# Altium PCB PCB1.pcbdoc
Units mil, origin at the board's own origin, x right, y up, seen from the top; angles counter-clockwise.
Board outline 2952.76 x 2952.76 mil, 2 copper layers (Top Layer, Bottom Layer), stack 62.206 mil thick; 24 components, 35 nets, 97 pads, 20 vias.
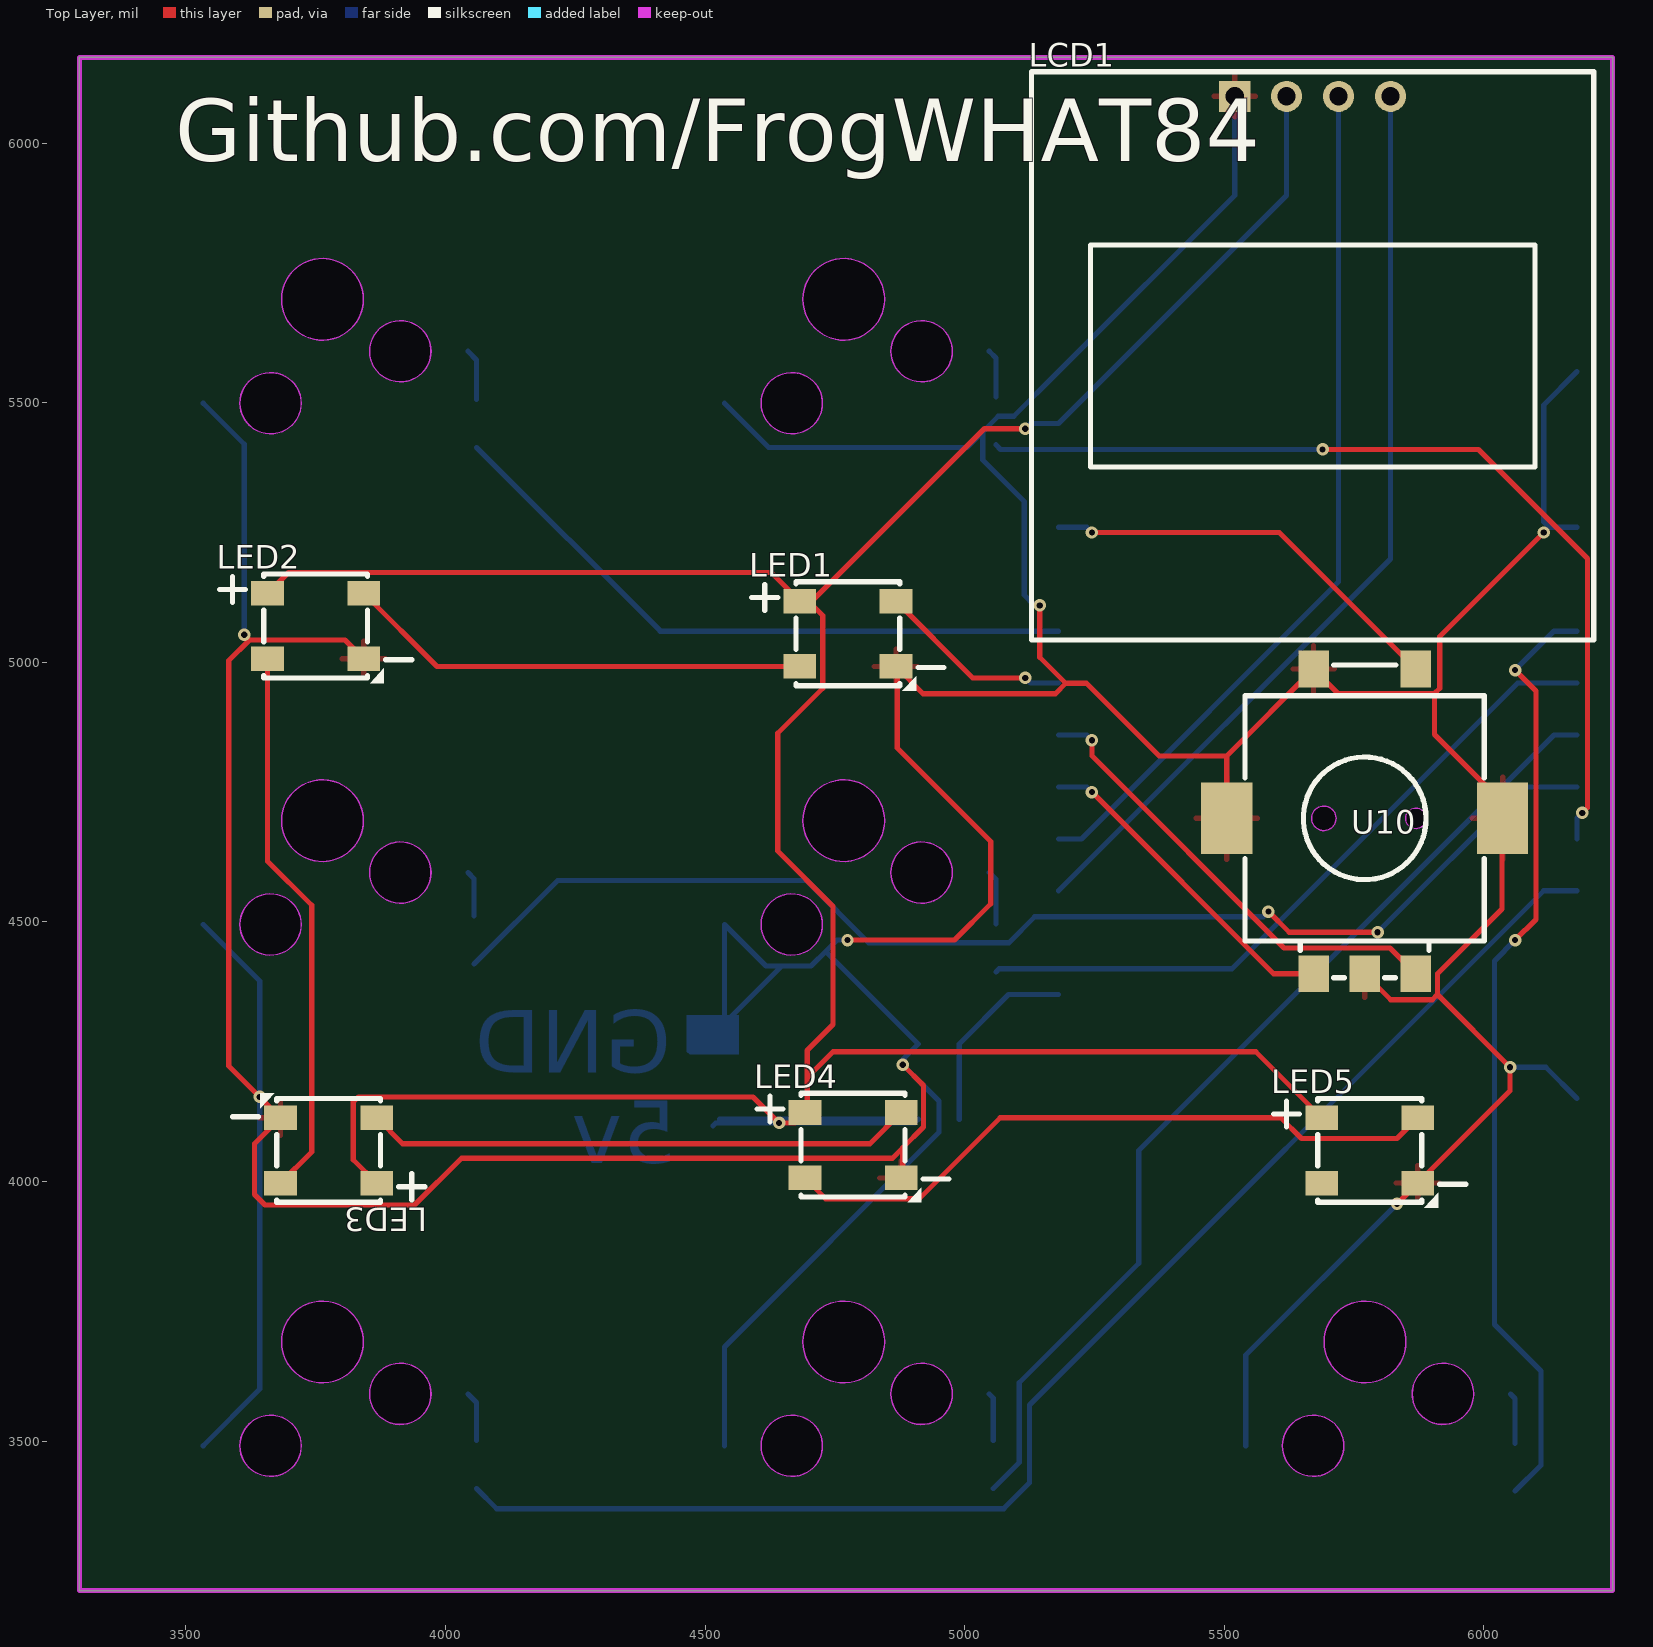
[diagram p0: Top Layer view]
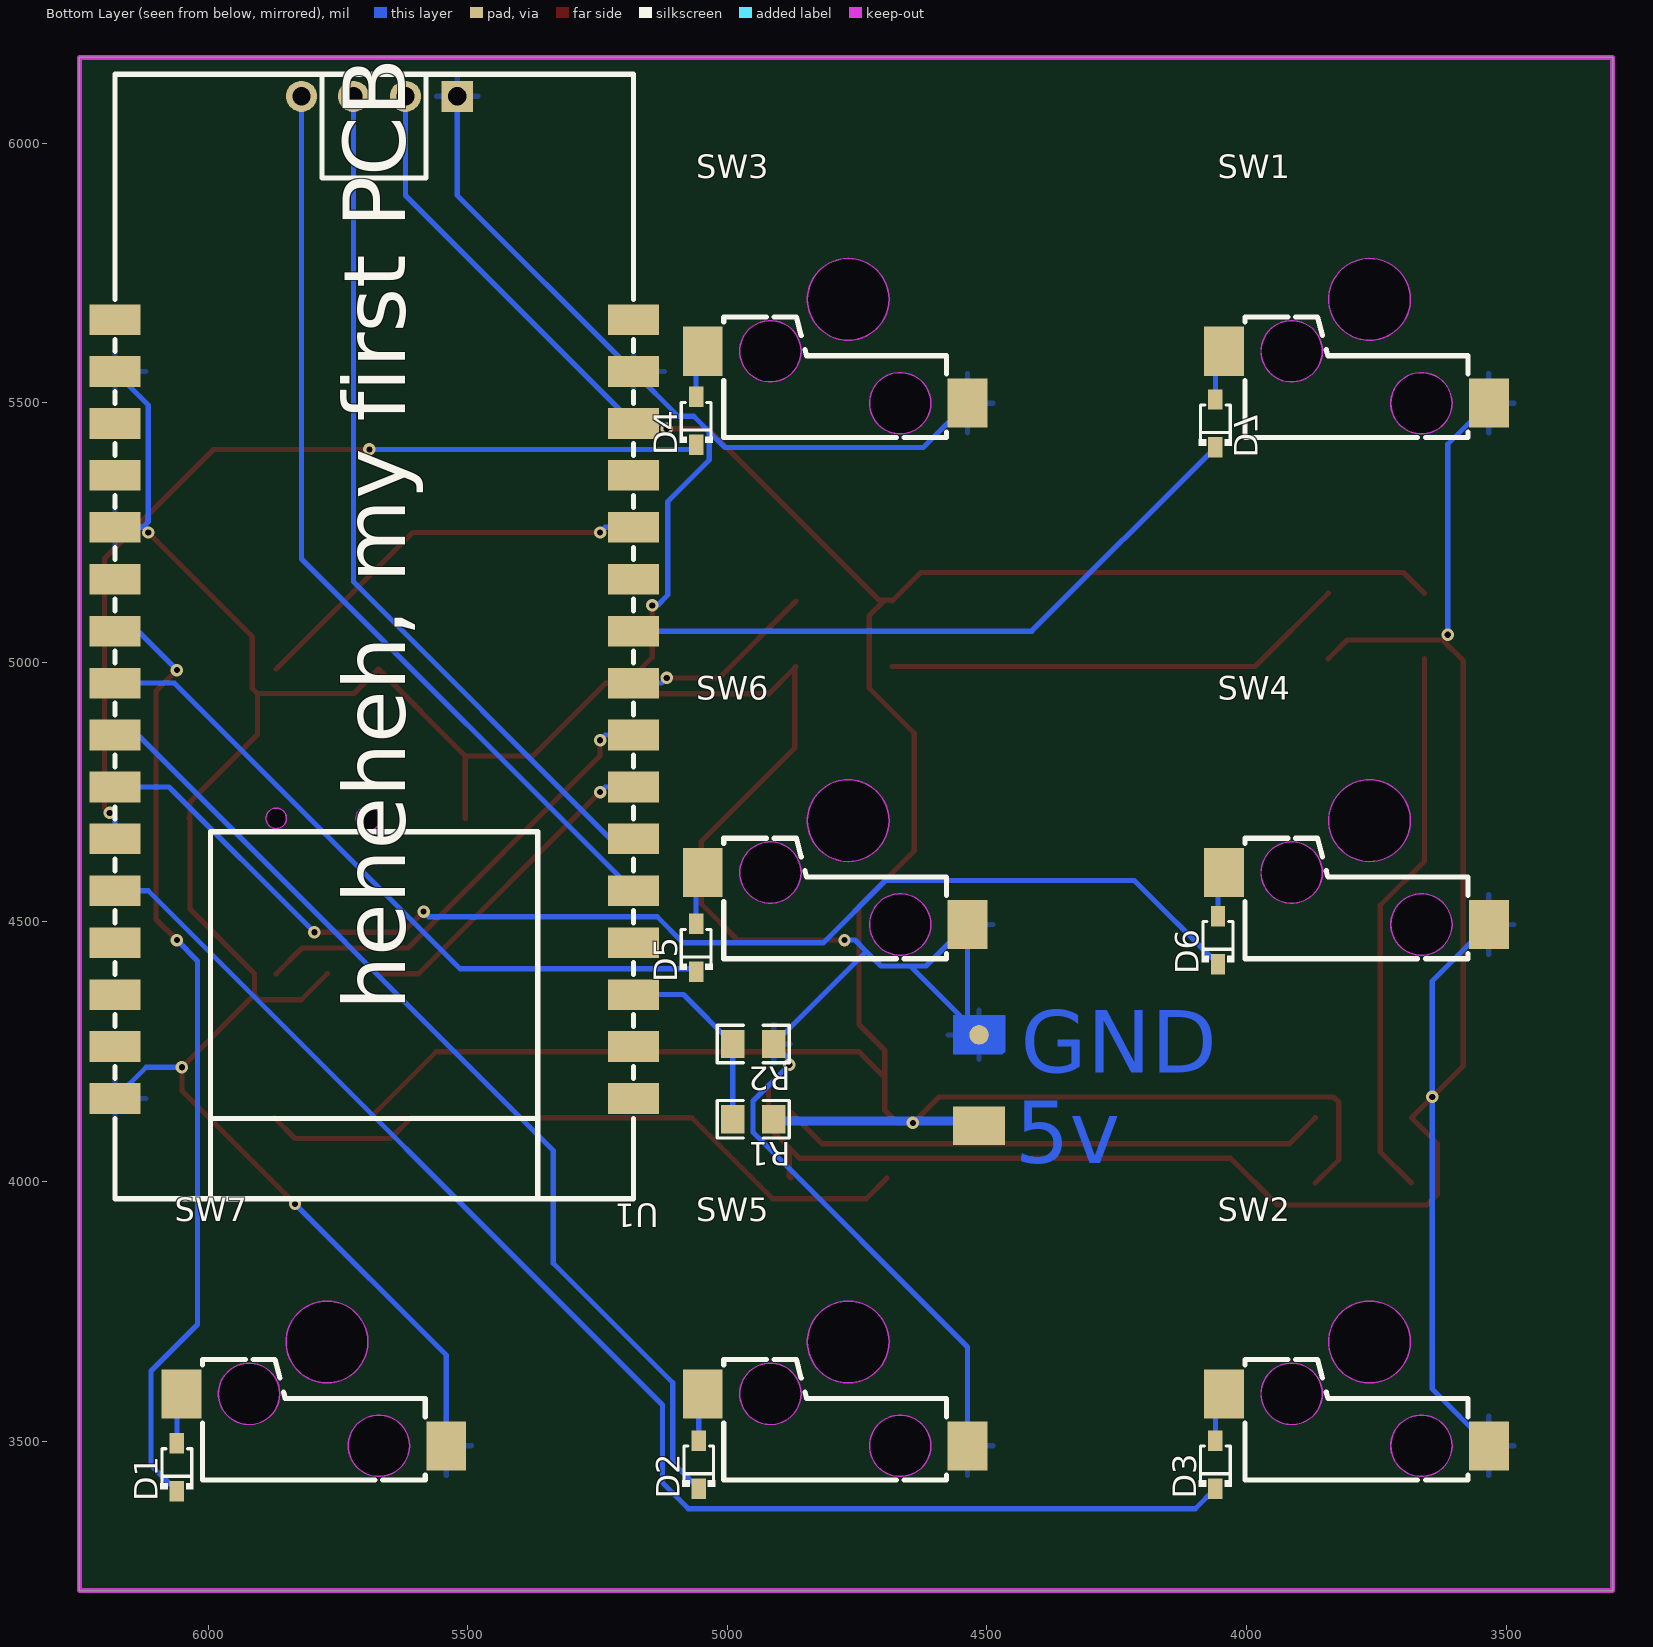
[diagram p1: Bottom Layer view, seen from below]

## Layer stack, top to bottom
Top Solder Mask Layer: solder mask 0.394, Dk 3.3
Top Layer: signal copper 1.379
Dielectric1: surface 59.449, FR4, Dk 4.5
Bottom Layer: signal copper 1.378
Bottom Solder Mask Layer: solder mask 0.394, Dk 3.3

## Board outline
3295,6165 3295,3212.24 6247.76,3212.24 6247.76,6165

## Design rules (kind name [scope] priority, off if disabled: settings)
BoardOutlineClearance copperThickness1oz [All] p0: genericclearance=10 ignorepadtopadclearanceinfootprint=FALSE except(0: Arc-SplitContinuation Track-SplitContinuation SMDPad-SplitContinuation THPad-SplitContinuation Via-SplitContinuation Fill-SplitContinuation Poly-SplitContinuation Region-SplitContinuation Text-SplitContinuation)
BoardOutlineClearance copperThickness2oz [All] p0: genericclearance=10 ignorepadtopadclearanceinfootprint=FALSE except(0: Arc-SplitContinuation Track-SplitContinuation SMDPad-SplitContinuation THPad-SplitContinuation Via-SplitContinuation Fill-SplitContinuation Poly-SplitContinuation Region-SplitContinuation Text-SplitContinuation)
BoardOutlineClearance otherClearance [All] p0: genericclearance=10 ignorepadtopadclearanceinfootprint=FALSE except(0: Arc-SplitContinuation Track-SplitContinuation SMDPad-SplitContinuation THPad-SplitContinuation Via-SplitContinuation Fill-SplitContinuation Poly-SplitContinuation Region-SplitContinuation Text-SplitContinuation)
Clearance copperThickness1oz [All] p1: gap=7 ignorepadtopadclearanceinfootprint=FALSE
Clearance copperThickness2oz [(InNet('+5V'))] p1: gap=7 ignorepadtopadclearanceinfootprint=FALSE
Clearance otherClearance [All] p1: gap=7 ignorepadtopadclearanceinfootprint=FALSE
DiffPairsRouting differentialPair [All] p1: maxuncoupledlength=10 minlimit=6 maxlimit=Infinity mostfreqgap=6 toplayer_minwidth=5 toplayer_prefwidth=10 toplayer_maxwidth=100 bottomlayer_minwidth=5 bottomlayer_prefwidth=10 bottomlayer_maxwidth=100
PasteMaskExpansion pasteMaskExpansion [All] p1: expansion=0
PlaneConnect innerPlane [All] p1: planeconnectstyle=Relief reliefexpansion=20 reliefentries=4 reliefconductorwidth=10 reliefairgap=10
PolygonConnect copperRegion [All] p1: connectstyle=Relief reliefentries=4 reliefconductorwidth=10 polygonreliefangle="90 Angle" airgapwidth=10
RoutingVias viaSize [All] p1: viastyle="Through Hole" holewidth=12.0078 minholewidth=11.811 maxholewidth=248.0314 width=12.0078 minwidth=11.811 maxwidth=248.0314
SolderMaskExpansion solderMaskExpansion [IsVia] p1: useseparateexpansions=TRUE expansion=-1000 expansionbottom=-1000
SolderMaskExpansion solderMaskExpansion [All] p2: useseparateexpansions=TRUE expansion=2 expansionbottom=2
Width copperThickness1oz [All] p1: maxlimit=100 minlimit=5 preferedwidth=10
Width copperThickness2oz [All] p1: maxlimit=100 minlimit=8 preferedwidth=10

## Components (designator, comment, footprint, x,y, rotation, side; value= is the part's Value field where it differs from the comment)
D1 "1N4148WS" SOD-323_L1.8-W1.3-LS2.5-RD#1 6060,3450 r90 bottom
D2 "1N4148WS" SOD-323_L1.8-W1.3-LS2.5-RD#1 5055,3455 r90 bottom
D3 "1N4148WS" SOD-323_L1.8-W1.3-LS2.5-RD#1 4060,3455 r90 bottom
D4 "1N4148WS" SOD-323_L1.8-W1.3-LS2.5-RD#1 5060,5465 r90 bottom
D5 "1N4148WS" SOD-323_L1.8-W1.3-LS2.5-RD#1 5060,4450 r90 bottom
D6 "1N4148WS" SOD-323_L1.8-W1.3-LS2.5-RD#1 4055,4465 r90 bottom
D7 "1N4148WS" SOD-323_L1.8-W1.3-LS2.5-RD#2 4060,5460 r270 bottom
LCD1 "SSD1306" SSD1306 5640,5595 r0 top
LED1 "WS2812B-V6" LED-SMD_4P-L5.0-W5.0-TL-A 4775,5055 r0 top
LED2 "WS2812B-V6" LED-SMD_4P-L5.0-W5.0-TL-A 3750,5070 r0 top
LED3 "WS2812B-V6" LED-SMD_4P-L5.0-W5.0-TL-A 3775,4060 r180 top
LED4 "WS2812B-V6" LED-SMD_4P-L5.0-W5.0-TL-A 4785,4070 r0 top
LED5 "WS2812B-V6" LED-SMD_4P-L5.0-W5.0-TL-A 5780,4060 r0 top
R1 "100K" R0805 4950,4120 r0 bottom
R2 "100K" R0805 4950,4265 r0 bottom
SW1 "SW-5" SW-SMD_KAILH-SOCKET_C9900019772 3762.44,5697.56 r180 bottom
SW2 "SW-5" SW-SMD_KAILH-SOCKET_C9900019772 3762.44,3689.68 r180 bottom
SW3 "SW-5" SW-SMD_KAILH-SOCKET_C9900019772 4766.38,5697.56 r180 bottom
SW4 "SW-5" SW-SMD_KAILH-SOCKET_C9900019772 3762.44,4693.62 r180 bottom
SW5 "SW-5" SW-SMD_KAILH-SOCKET_C9900019772 4766.38,3689.68 r180 bottom
SW6 "SW-5" SW-SMD_KAILH-SOCKET_C9900019772 4766.38,4693.62 r180 bottom
SW7 "SW-5" SW-SMD_KAILH-SOCKET_C9900019772 5770.31,3689.68 r180 bottom
U1 "ESP32-C6-DEV-KIT-N8 COPY" COMM-SMD_L55.0-W25.4_ESP32-C6-DEV-KIT-N8 5680,4910 r0 bottom
U10 "EC1106S" SW-SMD_EC1106S 5770.31,4693.62 r0 top

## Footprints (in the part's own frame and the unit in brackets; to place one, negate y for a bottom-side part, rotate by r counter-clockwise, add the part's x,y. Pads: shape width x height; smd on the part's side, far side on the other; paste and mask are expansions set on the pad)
COMM-SMD_L55.0-W25.4_ESP32-C6-DEV-KIT-N8 [mm]
  rect 2.5x1.5 smd paste+0 mask+0.051: 1(-12.68,19.05) 2(-12.68,16.51) 3(-12.68,13.97) 4(-12.68,11.43) 5(-12.68,8.89) 6(-12.68,6.35) 7(-12.68,3.81) 8(-12.68,1.27) 9(-12.68,-1.27) 10(-12.68,-3.81) 11(-12.68,-6.35) 12(-12.68,-8.89) 13(-12.68,-11.43) 14(-12.68,-13.97) 15(-12.68,-16.51) 16(-12.68,-19.05) 17(12.68,-19.05) 18(12.68,-16.51) 19(12.68,-13.97) 20(12.68,-11.43) 21(12.68,-8.89) 22(12.68,-6.35) 23(12.68,-3.81) 24(12.68,-1.27) 25(12.68,1.27) 26(12.68,3.81) 27(12.68,6.35) 28(12.68,8.89) 29(12.68,11.43) 30(12.68,13.97) 31(12.68,16.51) 32(12.68,19.05)
  silkscreen extent -12.68,-31.05 12.68,23.95
LED-SMD_4P-L5.0-W5.0-TL-A [mm]
  rect 1.6x1.2 smd paste+0 mask+0.05: 1(-2.35,1.6) 2(-2.35,-1.6) 3(2.35,-1.6) 4(2.35,1.6)
  silkscreen extent -4.7,-2.79 4.7,2.54
R0805 [mm]
  rect 1.133x1.377 smd paste-100 mask+0.051: 1(-1,0) 2(1,0)
  silkscreen extent -1.76,-0.92 1.76,0.92
SOD-323_L1.8-W1.3-LS2.5-RD#1 [mm]
  rect 1x0.7 smd: 1(-1.172,0) 2(1.172,0)
  silkscreen extent -1.08,-0.8 0.9,0.8
SOD-323_L1.8-W1.3-LS2.5-RD#2 [mm]
  rect 1x0.7 smd: 1(1.172,0) 2(-1.172,0)
  silkscreen extent -0.9,-0.8 1.08,0.8
SSD1306 [mil]
  rect 60x60 hole 35 paste+0 mask+4: 1(-120,495)
  round 60 hole 35 paste+0 mask+4: 2(-20,495) 3(80,495) 4(180,495)
  silkscreen extent -511,-552 571,542
SW-SMD_EC1106S [mm]
  rect 1.5x1.8 smd paste+0 mask+0.05: 1(-2.5,-7.45) 2(0,-7.45) 3(2.5,-7.45) 4(2.5,7.45) 5(-2.5,7.45)
  rect 2.5x3.5 smd paste+0 mask+0.05: 6(-6.75,0.15) 7(6.75,0.15)
  Board Outline Layer circle w0.003: c-2,0.15 r0.6
  Board Outline Layer circle w0.003: c2.5,0.15 r0.5
  Board Outline Layer region: -1.4,0.15 -1.459,-0.11 -1.626,-0.319 -1.866,-0.435 -2.134,-0.435 -2.374,-0.319 -2.541,-0.11 -2.6,0.15 -2.6,0.15 -2.541,0.41 -2.374,0.619 -2.134,0.735 -1.866,0.735 -1.626,0.619 -1.459,0.41 -1.4,0.15
  Board Outline Layer region: -1.4,0.15 -1.409,0.046 -1.436,-0.055 -1.48,-0.15 -1.54,-0.236 -1.614,-0.31 -1.7,-0.37 -1.795,-0.414 -1.896,-0.441 -2,-0.45 -2.104,-0.441 -2.205,-0.414 -2.3,-0.37 -2.386,-0.31 -2.46,-0.236 -2.52,-0.15 -2.564,-0.055 -2.591,0.046 -2.6,0.15 -2.591,0.254 -2.564,0.355 -2.52,0.45 -2.46,0.536 -2.386,0.61 -2.3,0.67 -2.205,0.714 -2.104,0.741 -2,0.75 -1.896,0.741 -1.795,0.714 -1.7,0.67 -1.614,0.61 -1.54,0.536 -1.48,0.45 -1.436,0.355 -1.409,0.254
  Board Outline Layer region: 3,0.15 2.951,-0.067 2.812,-0.241 2.611,-0.337 2.389,-0.337 2.188,-0.241 2.05,-0.067 2,0.15 2,0.15 2.05,0.367 2.188,0.541 2.389,0.637 2.611,0.637 2.812,0.541 2.951,0.367 3,0.15
  Board Outline Layer region: 3,0.15 2.991,0.052 2.962,-0.041 2.916,-0.128 2.854,-0.204 2.778,-0.266 2.691,-0.312 2.598,-0.34 2.5,-0.35 2.403,-0.34 2.309,-0.312 2.222,-0.266 2.147,-0.204 2.084,-0.128 2.038,-0.041 2.01,0.052 2,0.15 2.01,0.248 2.038,0.341 2.084,0.428 2.147,0.504 2.222,0.566 2.309,0.612 2.403,0.64 2.5,0.65 2.598,0.64 2.691,0.612 2.778,0.566 2.854,0.504 2.916,0.428 2.962,0.341 2.991,0.248
  Multi-Layer board cut-out: -1.4,0.15 -1.459,-0.11 -1.626,-0.319 -1.866,-0.435 -2.134,-0.435 -2.374,-0.319 -2.541,-0.11 -2.6,0.15 -2.6,0.15 -2.541,0.41 -2.374,0.619 -2.134,0.735 -1.866,0.735 -1.626,0.619 -1.459,0.41 -1.4,0.15
  Multi-Layer board cut-out: 3,0.15 2.951,-0.067 2.812,-0.241 2.611,-0.337 2.389,-0.337 2.188,-0.241 2.05,-0.067 2,0.15 2,0.15 2.05,0.367 2.188,0.541 2.389,0.637 2.611,0.637 2.812,0.541 2.951,0.367 3,0.15
  silkscreen extent -5.85,-7.65 5.85,7.65
SW-SMD_KAILH-SOCKET_C9900019772 [mm]
  rect 1.95x2.4 smd paste+0 mask+0.05: 1(-7.132,-2.503) 2(5.818,-5.043)
  Board Outline Layer circle w0.003: c-0.017,0.037 r2
  Board Outline Layer circle w0.003: c-3.827,-2.503 r1.5
  Board Outline Layer circle w0.003: c2.523,-5.043 r1.5
  Board Outline Layer region: -2.017,0.037 -1.819,-0.831 -1.264,-1.527 -0.462,-1.913 0.428,-1.913 1.23,-1.527 1.785,-0.831 1.983,0.037 1.983,0.037 1.785,0.905 1.23,1.601 0.428,1.987 -0.462,1.987 -1.264,1.601 -1.819,0.905 -2.017,0.037
  Board Outline Layer region: -2.017,0.037 -2.007,-0.159 -1.978,-0.353 -1.931,-0.544 -1.865,-0.728 -1.781,-0.906 -1.68,-1.074 -1.563,-1.232 -1.431,-1.377 -1.286,-1.509 -1.128,-1.626 -0.96,-1.727 -0.782,-1.811 -0.597,-1.877 -0.407,-1.925 -0.213,-1.953 -0.017,-1.963 0.179,-1.953 0.373,-1.925 0.564,-1.877 0.748,-1.811 0.926,-1.727 1.094,-1.626 1.252,-1.509 1.397,-1.377 1.529,-1.232 1.646,-1.074 1.747,-0.906 1.831,-0.728 1.897,-0.544 1.945,-0.353 1.973,-0.159 1.983,0.037 1.973,0.233 1.945,0.427 1.897,0.618 1.831,0.802 1.747,0.98 1.646,1.148 1.529,1.306 1.397,1.451 1.252,1.583 1.094,1.7 0.926,1.801 0.748,1.885 0.564,1.951 0.373,1.999 0.179,2.027 -0.017,2.037 -0.213,2.027 -0.407,1.999 -0.597,1.951 -0.782,1.885 -0.96,1.801 -1.128,1.7 -1.286,1.583 -1.431,1.451 -1.563,1.306 -1.68,1.148 -1.781,0.98 -1.865,0.802 -1.931,0.618 -1.978,0.427 -2.007,0.233
  Board Outline Layer region: -5.327,-2.503 -5.178,-3.154 -4.762,-3.676 -4.161,-3.965 -3.493,-3.965 -2.892,-3.676 -2.475,-3.154 -2.327,-2.503 -2.327,-2.503 -2.475,-1.852 -2.892,-1.33 -3.493,-1.041 -4.161,-1.041 -4.762,-1.33 -5.178,-1.852 -5.327,-2.503
  Board Outline Layer region: -5.327,-2.503 -5.317,-2.677 -5.286,-2.849 -5.236,-3.016 -5.167,-3.176 -5.08,-3.327 -4.976,-3.467 -4.856,-3.594 -4.723,-3.706 -4.577,-3.802 -4.421,-3.88 -4.257,-3.94 -4.087,-3.98 -3.914,-4 -3.74,-4 -3.566,-3.98 -3.397,-3.94 -3.233,-3.88 -3.077,-3.802 -2.931,-3.706 -2.798,-3.594 -2.678,-3.467 -2.574,-3.327 -2.486,-3.176 -2.417,-3.016 -2.367,-2.849 -2.337,-2.677 -2.327,-2.503 -2.337,-2.329 -2.367,-2.157 -2.417,-1.99 -2.486,-1.83 -2.574,-1.679 -2.678,-1.539 -2.798,-1.412 -2.931,-1.3 -3.077,-1.204 -3.233,-1.126 -3.397,-1.066 -3.566,-1.026 -3.74,-1.006 -3.914,-1.006 -4.087,-1.026 -4.257,-1.066 -4.421,-1.126 -4.577,-1.204 -4.723,-1.3 -4.856,-1.412 -4.976,-1.539 -5.08,-1.679 -5.167,-1.83 -5.236,-1.99 -5.286,-2.157 -5.317,-2.329
  Board Outline Layer region: 1.023,-5.043 1.172,-5.694 1.588,-6.216 2.189,-6.505 2.857,-6.505 3.458,-6.216 3.875,-5.694 4.023,-5.043 4.023,-5.043 3.875,-4.392 3.458,-3.87 2.857,-3.581 2.189,-3.581 1.588,-3.87 1.172,-4.392 1.023,-5.043
  Board Outline Layer region: 1.023,-5.043 1.033,-5.217 1.064,-5.389 1.114,-5.556 1.183,-5.716 1.27,-5.867 1.374,-6.007 1.494,-6.134 1.627,-6.246 1.773,-6.342 1.929,-6.42 2.093,-6.48 2.263,-6.52 2.436,-6.54 2.61,-6.54 2.784,-6.52 2.953,-6.48 3.117,-6.42 3.273,-6.342 3.419,-6.246 3.552,-6.134 3.672,-6.007 3.776,-5.867 3.864,-5.716 3.933,-5.556 3.983,-5.389 4.013,-5.217 4.023,-5.043 4.013,-4.869 3.983,-4.697 3.933,-4.53 3.864,-4.37 3.776,-4.219 3.672,-4.079 3.552,-3.952 3.419,-3.84 3.273,-3.744 3.117,-3.666 2.953,-3.606 2.784,-3.566 2.61,-3.546 2.436,-3.546 2.263,-3.566 2.093,-3.606 1.929,-3.666 1.773,-3.744 1.627,-3.84 1.494,-3.952 1.374,-4.079 1.27,-4.219 1.183,-4.37 1.114,-4.53 1.064,-4.697 1.033,-4.869
  Multi-Layer board cut-out: -2.017,0.037 -1.819,-0.831 -1.264,-1.527 -0.462,-1.913 0.428,-1.913 1.23,-1.527 1.785,-0.831 1.983,0.037 1.983,0.037 1.785,0.905 1.23,1.601 0.428,1.987 -0.462,1.987 -1.264,1.601 -1.819,0.905 -2.017,0.037
  Multi-Layer board cut-out: -5.327,-2.503 -5.178,-3.154 -4.762,-3.676 -4.161,-3.965 -3.493,-3.965 -2.892,-3.676 -2.475,-3.154 -2.327,-2.503 -2.327,-2.503 -2.475,-1.852 -2.892,-1.33 -3.493,-1.041 -4.161,-1.041 -4.762,-1.33 -5.178,-1.852 -5.327,-2.503
  Multi-Layer board cut-out: 1.023,-5.043 1.172,-5.694 1.588,-6.216 2.189,-6.505 2.857,-6.505 3.458,-6.216 3.875,-5.694 4.023,-5.043 4.023,-5.043 3.875,-4.392 3.458,-3.87 2.857,-3.581 2.189,-3.581 1.588,-3.87 1.172,-4.392 1.023,-5.043
  silkscreen extent -6.11,-6.72 4.79,-0.82

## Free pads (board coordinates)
  round 37.44 smd far side: 1(4515.08,4282.56)
  rect 100x75 smd far side: 2(4515,4107.5)

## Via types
v1: diameter 24.02, hole 12, Top Layer to Bottom Layer, 20 vias

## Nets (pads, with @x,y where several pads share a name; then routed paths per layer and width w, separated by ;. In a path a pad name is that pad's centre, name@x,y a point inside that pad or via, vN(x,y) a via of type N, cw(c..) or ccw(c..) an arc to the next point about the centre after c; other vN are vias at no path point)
$1N48: R1.2 R2.2 U1.3 | length 375.8
  Bottom Layer w10: R1.2 R2.2 5084.37,4360 U1.3
$1N108: LED1.2 LED2.4 | length 898.4
  Top Layer w10: LED2.4 3983.51,4992 LED1.2
$1N110: LED2.2 LED3.4 | length 1070.1
  Top Layer w10: LED2.2 3657.48,4617 3742.48,4532 3742.48,4057 LED3.4
$1N113: LED3.2 LED4.4 | length 1055.6
  Top Layer w10: LED3.2 3917.52,4073 4817.52,4073 LED4.4
$1N123: LED5.2
$1N128: LED4.2 LED5.4 | length 1294.4
  Top Layer w10: LED4.2 4732.48,3967 4912.48,3967 5068.47,4123 5608.47,4123 5648.47,4083 5832.52,4083 LED5.4
$1N129: D7.2 SW1.1 | length 99.8
  Bottom Layer w10: SW1.1 4060,5582.25 D7.2
$1N132: D3.2 SW2.1 | length 96.9
  Bottom Layer w10: SW2.1 4060,3574.37 D3.2
$1N133: D4.2 SW3.1 | length 93.2
  Bottom Layer w10: SW3.1 5060,5586.18 D4.2
$1N136: D6.2 SW4.1 | length 88.8
  Bottom Layer w10: SW4.1 4055,4583.31 D6.2
$1N138: D2.2 SW5.1 | length 93.2
  Bottom Layer w10: SW5.1 5055,3583.31 D2.2
$1N139: D5.2 SW6.1 | length 104.2
  Bottom Layer w10: SW6.1 5060,4582.24 D5.2
$1N141: D1.2 SW7.1 | length 98.7
  Bottom Layer w10: SW7.1 6060,3582.25 D1.2
+5V: LCD1.2 LED1.1 LED2.1 LED3.1 LED4.1 LED5.1 pad.2 R1.1 U1.14 | length 6544
  Top Layer w10: LED2.1 3697.48,5172.99 4627.48,5172.99 LED1.1 4684.48,5119.99 LED1.1@4696.58,5119.99 ; LED3.1 3822.48,4042.04 3822.48,4153 3832.48,4163 4592.48,4163 v1(4642.48,4113) 4672.48,4113 LED4.1 4696.58,4137.09 4696.58,4200 ; v1(5116.58,5449.99) 5037.84,5449.99 4707.84,5119.99 LED1.1@4696.58,5119.99 ; LED5.1 5560.48,4250 4746.58,4250 4696.58,4200 ; 4696.58,4200 4696.58,4252.52 4746.58,4302.52 4746.58,4530 4640,4636.57 4640,4863.42 4726.58,4949.99 4726.58,5089.99 LED1.1@4696.58,5119.99
  Bottom Layer w10: pad.2 4520.5,4113 v1(4642.48,4113) 4903.63,4113 R1.1 pad.2@4527.5,4120 ; v1(5116.58,5449.99) 5126.58,5459.99 U1.14 5620,5899.21 LCD1.2
GND: LCD1.1 LED1.3 LED2.3 LED3.3 LED4.3 LED5.3 pad.1 R2.1 SW1.2 SW2.2 SW3.2 SW4.2 SW5.2 SW6.2 SW7.2 U1.15 U1.18 U1.21 U1.32 U10.2 U10.5 U10.6 U10.7 | length 13507
  Top Layer w10: v1(3612.48,5052.99) 3622.48,5042.99 ; LED2.3 3806.53,5042.99 3622.48,5042.99 ; v1(4774.25,4465.08) 4980.08,4465.08 5050,4535 5050,4655 4870,4835 LED1.3@4870,4989.52 ; LED4.3 4880.63,4010.11 4880.63,4065 ; v1(4880.63,4225) 4920.63,4185 4920.63,4105 4880.63,4065 ; v1(5144.56,5109.6) 5144.56,5009.6 5194.56,4959.6 ; U10.6 5504.56,4819.6 ; U10.2 5820.31,4350.32 5900.31,4350.32 5910.31,4360.32 ; v1(5832.52,3957) LED5.3 6050.31,4174.8 v1(6050.31,4220.32) 5910.31,4360.32 ; U10.7 U10.7@6035,4700 ; v1(6115,5249.99) 5915,5049.99 5915,4949.99 5905,4939.99 ; 3622.48,5042.99 3582.48,5002.99 3582.48,4223 v1(3642.48,4163) LED3.3 3632.48,4073 3632.48,3975 3652.48,3955 3940.63,3955 4030.63,4045 4860.63,4045 4880.63,4065 ; LED1.3@4870,4989.52 LED1.3 LED1.3@4870,4989.52 ; LED1.3@4870,4989.52 4919.93,4939.6 5174.56,4939.6 5194.56,4959.6 ; 5194.56,4959.6 5234.56,4959.6 5374.56,4819.6 5504.56,4819.6 ; 5504.56,4819.6 U10.5 5718.83,4939.99 5905,4939.99 ; 5905,4939.99 5905,4861.25 6035,4731.25 U10.7@6035,4700 ; 5910.31,4360.32 5910.31,4400.32 6035,4525 U10.7@6035,4700
  Bottom Layer w10: SW2.2 3642.48,3600.24 v1(3642.48,4163) 3642.48,4385.98 SW4.2 ; SW1.2 3612.48,5419.92 v1(3612.48,5052.99) ; pad.1@4515,4282.5 4537.32,4304.82 ; SW5.2 4537.32,3681.69 4950.63,4095 4950.63,4155 v1(4880.63,4225) 4880.63,4235 R2.1 4734.25,4441.38 4734.25,4445.08 ; SW3.2 4622.57,5413.77 5004.56,5413.77 5034.56,5443.77 ; v1(4774.25,4465.08) 4754.25,4465.08 4734.25,4445.08 ; v1(5144.56,5109.6) 5134.56,5109.6 5114.56,5129.6 5114.56,5309.6 5034.56,5389.6 5034.56,5443.77 ; LCD1.1 5520,5899.21 U1.15 5094.56,5473.77 5064.56,5473.77 5034.56,5443.77 ; SW7.2 5541.26,3665.75 v1(5832.52,3957) ; v1(6050.31,4220.32) 6118.9,4220.32 U1.32 ; v1(6115,5249.99) 6125,5259.99 ; U1.21 6125,5259.99 ; U1.18 6115,5495.78 6115,5269.99 6125,5259.99 ; 4537.32,4304.82 SW6.2 4617.32,4415.08 4644.25,4415.08 ; 4537.32,4304.82 4644.25,4411.75 4644.25,4415.08 ; 4644.25,4415.08 4704.25,4415.08 4734.25,4445.08
GPIO_0: U1.7 U10.1 | length 640.1
  Top Layer w10: v1(5245,4750) 5594.68,4400.32 U10.1
  Bottom Layer w10: U1.7 5235,4760 v1(5245,4750)
GPIO_1: U1.8 U10.3 | length 895.9
  Top Layer w10: v1(5245,4850) 5245,4820 5615,4450 5819.05,4450 U10.3
  Bottom Layer w10: U1.8 5235,4860 v1(5245,4850)
GPIO_2: U1.12 U10.4 | length 801.1
  Top Layer w10: v1(5245,5249.99) 5605.67,5249.99 U10.4
  Bottom Layer w10: U1.12 5235,5259.99 v1(5245,5249.99)
GPIO_6: LCD1.4 U1.5 | length 1794.8
  Bottom Layer w10: U1.5 5820,5199.21 LCD1.4
GPIO_7: LCD1.3 U1.6 | length 1679.2
  Bottom Layer w10: U1.6 5225,4660 5720,5155 LCD1.3
GPIO_8: LED1.4 U1.9 | length 378.7
  Top Layer w10: LED1.4 5015.51,4970 v1(5116.58,4970)
  Bottom Layer w10: v1(5116.58,4970) 5126.58,4960 U1.9
Kalih_1: D1.1 U1.23
KALIH_1:  | length 1839.1
  Top Layer w10: v1(6060,4465) 6100,4505 6100,4945 v1(6060,4985)
  Bottom Layer w10: 6060,3403.84 6110,3453.84 6110,3635.01 6020,3725 6020,4425 v1(6060,4465) ; v1(6060,4985) 6135,5060 6179.21,5060
Kalih_2: D5.1 U1.24
KALIH_2:  | length 1349.6
  Bottom Layer w10: 5060,4403.84 5066.17,4410 5515,4410 6065,4960 6179.21,4960
Kalih_3: D2.1 U1.25
KALIH_3:  | length 1942.7
  Bottom Layer w10: 5055,3408.84 5105,3458.84 5105,3612.52 5335,3842.52 5335,4060 6135,4860 6179.21,4860
Kalih_4: D6.1 U1.26
KALIH_4:  | length 2398.1
  Top Layer w10: v1(5585,4520) 5625,4480 v1(5795,4480)
  Bottom Layer w10: 4055,4418.84 4216.16,4580 4695,4580 4815,4460 5085,4460 5135,4510 5575,4510 v1(5585,4520) ; v1(5795,4480) 6075,4760 6179.21,4760
Kalih_5: D4.1 U1.27
KALIH_5:  | length 1778.1
  Top Layer w10: v1(5689.21,5410) 5989.21,5410 6199.21,5200 6199.21,4720 v1(6189.21,4710)
  Bottom Layer w10: 5060,5418.84 5068.84,5410 v1(5689.21,5410) ; 6179.21,4660 6179.21,4700 v1(6189.21,4710)
Kalih_6: D3.1 U1.28
KALIH_6:  | length 2716.1
  Bottom Layer w10: 4060,3408.84 4098.83,3370.01 5075,3370.01 5125,3420.01 5125,3570.01 6115,4560 6179.21,4560
Kalih_7: D7.1 U1.10
KALIH_7:  | length 1267.4
  Bottom Layer w10: 4060,5413.84 4413.84,5060 5180.79,5060
pads on no net: U1.1 U1.2 U1.4 U1.11 U1.13 U1.16 U1.17 U1.19 U1.20 U1.22 U1.29 U1.30 U1.31

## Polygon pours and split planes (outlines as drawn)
GND on Top Layer (solid, remove dead copper, pour order 0): 3240,6235 3240,3170 6315,3170 6315,6235
GND on Bottom Layer (solid, remove dead copper, pour order 2): 3150,6275 3150,3135 6280,3135 6280,6275
GND on Bottom Layer (solid, remove dead copper, pour order 4): 3000,6435 3000,3000 6585,3000 6585,6435

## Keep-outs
Board Outline Layer:
  the board outline again, w10

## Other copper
Bottom Layer:
  region net GND: 4465,4320 4565,4320 4565,4245 4470,4245 4465,4250
  text "GND" at 4435,4210 h120
  text "5v" at 4445,4035 h120

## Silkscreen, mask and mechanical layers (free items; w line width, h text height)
Top Silkscreen Layer:
  text "Github.com/FrogWHAT84" at 3480,5965 h120
Bottom Silkscreen Layer:
  text "heheheh, my first PCB" at 5620,4330 h120 r270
